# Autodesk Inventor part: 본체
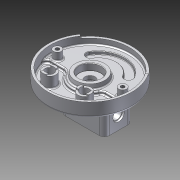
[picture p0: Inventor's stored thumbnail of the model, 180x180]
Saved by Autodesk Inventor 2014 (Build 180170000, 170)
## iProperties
Company: 한국ATC센터
Created: 2015-04
Part Number: 본체
Document SubType Name: Modeling
Designer: KYOUNG IL JANG
Density: 2.71 g/cm^3
Material: 알루미늄-6061
Mass: 1340.83 g
Surface Area: 1387.34 cm^2
Volume: 494.771 cm^3
Appearance: 매끄러움 - 흰색
Author: KYOUNG IL JANG
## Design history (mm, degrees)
sketch "스케치1"
  geometry: L1 (-59, -19)-(-59, 19); L2 (59, 19)-(59, -19); L3 (-41, 19)-(-41, -19); L4 (41, -19)-(41, 19); L5 (38.527, 33.023)-(55.442, 39.179); L6 (-38.527, 33.023)-(-55.442, 39.179); C1 r 90 at (0, 0); C2 r 95 at (0, 0); A1 r 59 centre (0, 19) between (59, 19) and (-59, 19); A2 r 59 centre (0, -19) between (-59, -19) and (59, -19); A3 r 41 centre (0, -19) between (-41, -19) and (41, -19); A4 r 41 centre (0, 19) between (41, 19) and (-41, 19); 2 further points
  constraints: 12 end point, 12 point on circle, 6 centre point, 4 tangent, 2 parallel, 2 point on line, 1 coincident, 1 horizontal alignment, 1 midpoint, 1 vertical, 1 vertical alignment, 3 other
  dimensions: "d2" = 180 diameter of C1; "d3" = 156 dimension on A2 A1; "d4" = 118 distance between parallel lines of L2 L1; "d5" = 18 distance between parallel lines of L2 L4; "d8" = 190 diameter of C2; "d124" = 110 deg dimension on A1.centre point (0, 0) L5.end; "d125" = 140 deg angle of L5 L6
extrude "돌출1" new body sketch "스케치1" distance "d6" = 14; taper "d7" = 0 deg
extrude "돌출2" join sketch "스케치1" distance "d9" = 13; taper "d10" = 0 deg
extrude "돌출3" cut sketch "스케치1" distance "d11" = 7; taper "d12" = 0 deg
sketch "스케치2"
  geometry: C1 r 11.5 at (0, 0); 1 further point
  constraints: 1 centre point, 1 coincident
  dimensions: "d13" = 23 diameter of C1
extrude "돌출4" cut sketch "스케치2" stored distance "d14" = 7; taper "d15" = 0 deg
fillet "모깎기1"
fillet "모깎기2"
sketch "스케치3"
  geometry: L1 (-73.724, 51.622)-(-77.819, 54.49); L2 (73.724, 51.622)-(77.819, 54.49); L3 (0, 0)-(0, -90); A1 r 95 centre (0, 0) between (-77.819, 54.49) and (77.819, 54.49) reference; A2 r 90 centre (0, 0) between (-73.724, 51.622) and (73.724, 51.622) reference; 1 further point
  constraints: 6 end point, 5 point on circle, 1 point on line, 1 vertical, 1 other
  dimensions: "d16" = 250 deg dimension on L2 L1
extrude "돌출5" join sketch "스케치3" distance "d17" = 5; taper "d18" = 0 deg
hole "구멍1" diameter "d21" = 50; stored, may be unused: countersink angle "d25" = 90 deg, drill point angle "d27" = 0 deg; dims "d19" = 10, "d20" = 10, "d22" = 6, "d23" = 4, "d24" = 2, "d26" = 5
fillet "모깎기3" dims "d28" = 0.3
fillet "모깎기5" dims "d30" = 3
sketch "스케치4"
  geometry: C1 r 35 at (0, 0); C2 r 25 at (0, 0); 1 further point
  constraints: 2 centre point, 1 coincident
  dimensions: "d32" = 70 diameter of C1 (derived); "d36" = 10 radial gap between concentric circles of C1 C2
extrude "돌출6" join sketch "스케치4" distance "d33" = 10; taper "d34" = 0 deg
feature "면 기울기2" dims angle "d37" = 10 deg
chamfer "모따기1" distance "d39" = 1; stored, may be unused: second distance "d40" = 2, angle "d41" = 45 deg
fillet "모깎기7" dims "d42" = 5
sketch "스케치5"
  geometry: L1 (-40.249, -12)-(-89.196, -12); L2 (40.249, -12)-(89.196, -12); A1 r 90 centre (0, 0) between (-89.196, -12) and (89.196, -12) reference; A2 r 42 centre (0, 0) between (-40.249, -12) and (40.249, -12); 1 further point
  constraints: 4 end point, 4 point on circle, 1 centre point, 1 collinear, 1 horizontal, 1 point on line
  dimensions: "d43" = 48 radial gap between concentric circles of A1 A2; "d44" = 12 distance from line of point (0, 0) L1
extrude "돌출7" cut sketch "스케치5" stored distance "d45" = 10; taper "d46" = 0 deg
fillet "모깎기8" dims "d47" = 10
chamfer "모따기2" distance "d49" = 1; stored, may be unused: second distance "d50" = 2, angle "d51" = 45 deg
sketch "스케치8"
  geometry: C1 r 9 at (74, 0); C2 r 9 at (-74, 0); A1 r 74 centre (0, 0) between (74, 0) and (-74, 0); 1 further point
  constraints: 3 centre point, 2 horizontal alignment, 2 point on circle, 1 coincident, 1 equal radius
  dimensions: "d64" = 18 diameter of C1; "d65" = 148 diameter of A1
extrude "돌출9" join sketch "스케치8" stored distance "d66" = 5; taper "d67" = 0 deg
sketch "스케치11"
  geometry: C1 r 15 at (40, -52); C2 r 15 at (-40, -52); 1 further point
  constraints: 2 centre point, 1 equal radius, 1 horizontal alignment
  dimensions: "d82" = 52 vertical distance of point (0, 0) C1.centre; "d83" = 30 diameter of C1; "d84" = 80 distance of C2.centre C1.centre; "d85" = 40 horizontal distance of point (0, 0) C1.centre (= 0.5 x d84)
extrude "돌출10" join sketch "스케치11" stored distance "d86" = 10; taper "d87" = 0 deg
node "구멍3"
node "구멍5"
hole "구멍6" diameter "d92" = 20; stored, may be unused: countersink angle "d96" = 90 deg, drill point angle "d98" = 118 deg; dims "d90" = 10, "d91" = 10, "d93" = 6, "d94" = 4, "d95" = 2, "d97" = 8
hole "구멍7" diameter "d101" = 20; stored, may be unused: countersink angle "d105" = 90 deg, drill point angle "d107" = 118 deg; dims "d99" = 10, "d100" = 10, "d102" = 6, "d103" = 4, "d104" = 2, "d106" = 8
fillet "모깎기13" dims "d108" = 3
sketch "스케치13"
  geometry: L1 (-20.252, -58)-(-26, -58); L2 (-42, -58)-(-47.748, -58); L3 (-20.252, -46)-(-26, -46); L4 (-42, -46)-(-47.748, -46); L5 (-108, -65.748)-(-108, -60); L6 (-108, -44)-(-108, -38.252); L7 (-120, -44)-(-120, -38.252); L8 (-120, -60)-(-120, -65.748); A1 r 15 centre (-34, -52) between (-20.252, -58) and (-47.748, -58) reference; A2 r 10 centre (-34, -52) between (-26, -58) and (-42, -58) reference; A3 r 15 centre (-114, -52) between (-108, -65.748) and (-108, -38.252) reference; A4 r 10 centre (-114, -52) between (-108, -60) and (-108, -44) reference; 1 further point
  constraints: 16 end point, 16 point on circle, 3 equal length, 3 point on line, 2 collinear, 1 horizontal, 1 perpendicular
  dimensions: "d114" = 12 distance between parallel lines of L4 L2; "d115" = 6 distance from line of A1.centre L2 (= 0.5 x d114); "d116" = 12 distance between parallel lines of L8 L5 (= d114); "d117" = 6 distance from line of A3.centre L5 (= d115)
extrude "돌출12" join sketch "스케치13" distance "d118" = 3; taper "d119" = 0 deg
fillet "모깎기14" dims "d120" = 1
sketch "스케치14"
  geometry: L1 (23, 32.5)-(-53, 32.5); L2 (-65, 20.5)-(-65, -20.5); L3 (-53, -32.5)-(23, -32.5); L4 (35, -20.5)-(35, 20.5); L5 (30, 20.5)-(30, -20.5); L6 (23, -27.5)-(-53, -27.5); L7 (-60, -20.5)-(-60, 20.5); L8 (-53, 27.5)-(23, 27.5); A1 r 12 centre (-53, -20.5) between (-65, -20.5) and (-53, -32.5); A2 r 12 centre (-53, 20.5) between (-53, 32.5) and (-65, 20.5); A3 r 12 centre (23, 20.5) between (35, 20.5) and (23, 32.5); A4 r 12 centre (23, -20.5) between (23, -32.5) and (35, -20.5); A5 r 7 centre (23, -20.5) between (23, -27.5) and (30, -20.5); A6 r 7 centre (-53, -20.5) between (-60, -20.5) and (-53, -27.5); A7 r 7 centre (-53, 20.5) between (-53, 27.5) and (-60, 20.5); A8 r 7 centre (23, 20.5) between (30, 20.5) and (23, 27.5); A9 r 6 centre (-23, -25) between (-17.546, -27.5) and (-28.454, -27.5); A10 r 6 centre (-23, 25) between (-28.454, 27.5) and (-17.546, 27.5); 6 further points
  constraints: 20 point on circle, 16 end point, 12 point on line, 10 centre point, 8 tangent, 4 equal radius, 4 parallel, 2 perpendicular, 1 horizontal, 1 horizontal alignment, 1 midpoint, 1 vertical alignment, 7 other
  dimensions: "d126" = 35 distance from line of point (0, 0) L4; "d127" = 65 distance of point (35, -32.5) point (35, 32.5); "d128" = 100 distance of point (35, 32.5) point (-65, 32.5); "d132" = 12 radius of A1; "d133" = 5 distance between parallel lines of L5 L4; "d141" = 42 distance from line of A9.centre L2; "d142" = 12 diameter of A9; "d143" = 50 distance of A10.centre A9.centre; "d144" = 25 vertical distance of point (0, 0) A9.centre (= 0.5 x d143)
extrude "돌출13" join sketch "스케치14" distance "d130" = 58; taper "d131" = 0 deg
fillet "모깎기16" dims "d145" = 3
hole "구멍8" diameter "d148" = 4.134; stored, may be unused: countersink angle "d152" = 90 deg, drill point angle "d154" = 118 deg; dims "d146" = 10, "d147" = 10, "d149" = 12, "d150" = 4, "d151" = 2, "d153" = 15
hole "구멍9" diameter "d157" = 4.134; stored, may be unused: countersink angle "d161" = 90 deg, drill point angle "d163" = 118 deg; dims "d155" = 10, "d156" = 10, "d158" = 12, "d159" = 4, "d160" = 2, "d162" = 15
sketch "스케치17"
  geometry: L1 (-58, 110.5)-(-58, -69.5) reference; C1 r 15 at (-29.5, 20.5); 1 further point
  constraints: 1 centre point, 1 horizontal alignment
  dimensions: "d164" = 28.5 distance from line of C1.centre L1; "d165" = 30 diameter of C1
extrude "돌출16" join sketch "스케치17" distance "d166" = 28; taper "d167" = 0 deg
fillet "모깎기17" dims "d168" = 1
hole "구멍10" diameter "d171" = 22; stored, may be unused: countersink angle "d175" = 90 deg, drill point angle "d177" = 118 deg; dims "d169" = 10, "d170" = 10, "d172" = 12, "d173" = 26, "d174" = 4, "d176" = 15
node "솔리드1"
sketch "스케치9"
  geometry: 1 further point
hole "구멍2" sketch "스케치9" diameter "d68" = 8.376; stored, may be unused: countersink angle "d72" = 90 deg, drill point angle "d74" = 120 deg; dims "d69" = 16, "d70" = 4, "d71" = 2, "d73" = 21
sketch "스케치10"
  geometry: 1 further point
hole "구멍4" sketch "스케치10" diameter "d75" = 8.376; stored, may be unused: countersink angle "d79" = 90 deg, drill point angle "d81" = 120 deg; dims "d76" = 16, "d77" = 4, "d78" = 2, "d80" = 21
